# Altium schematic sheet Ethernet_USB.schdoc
size 298 x 196 mm
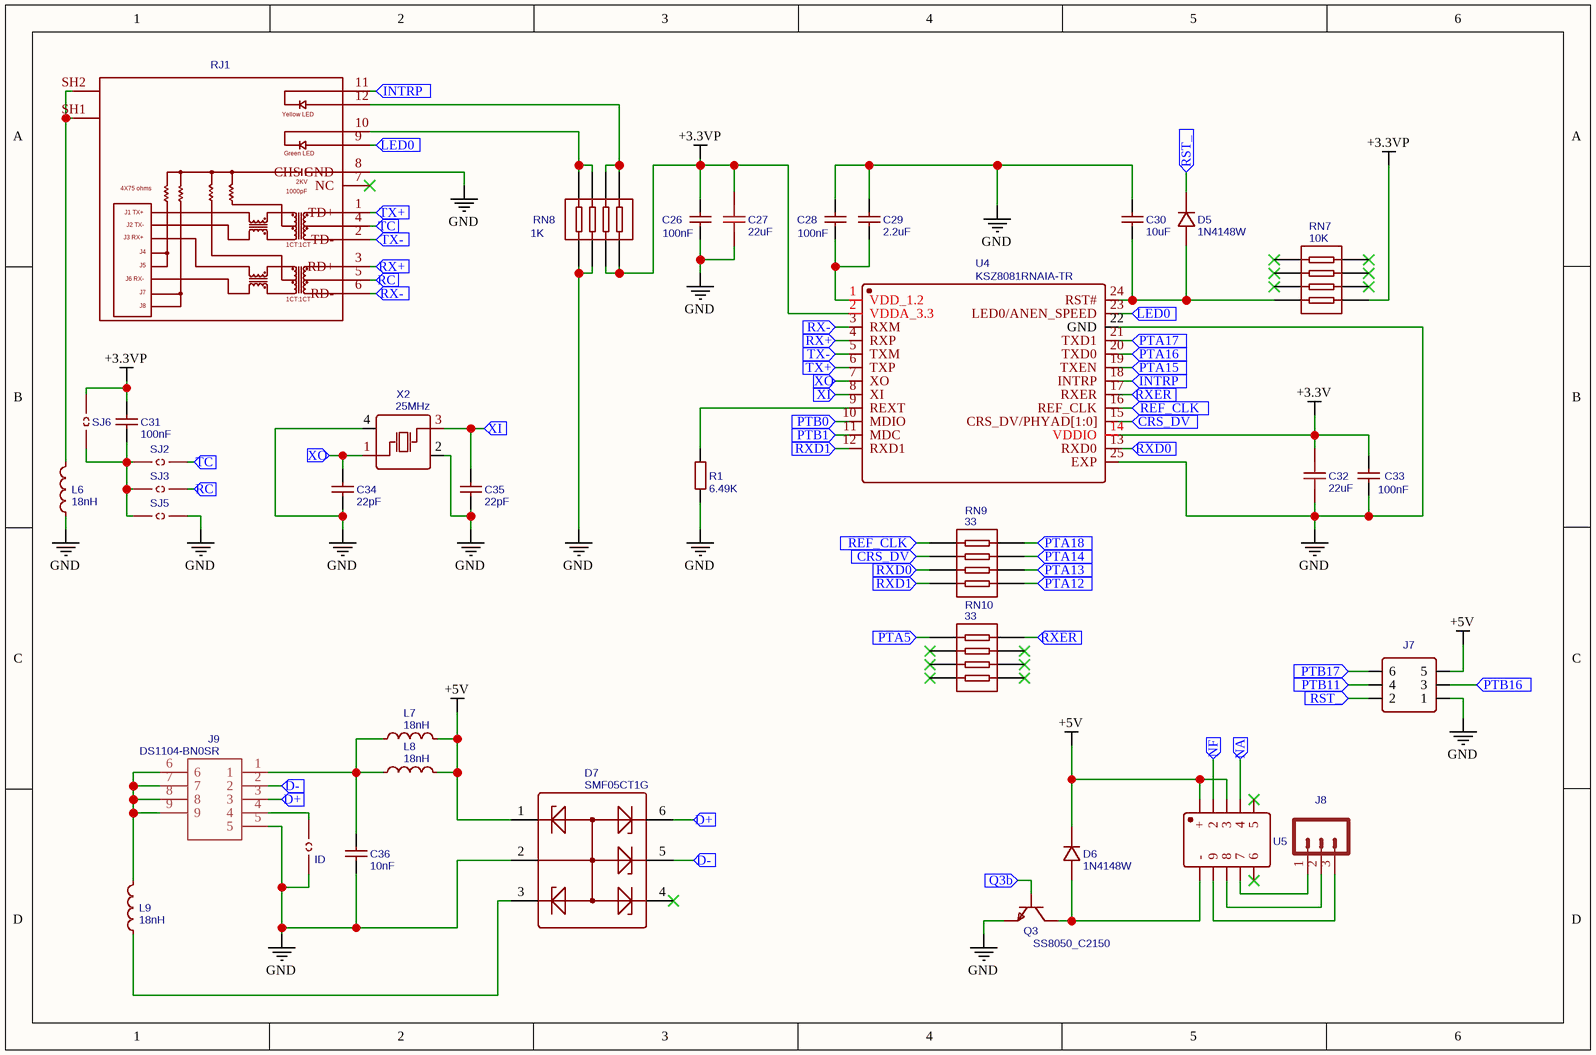
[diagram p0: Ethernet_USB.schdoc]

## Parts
C26  100nF  [C0402]
C27  22uF  [C0805]
C28  100nF  [C0402]
C29  2.2uF  [C0603]
C30  10uF  [C0805]
C31  100nF  [C0402]
C32  22uF  [C0805]
C33  100nF  [C0402]
C34  22pF  [C0402]
C35  22pF  [C0402]
C36  10nF  [C0402]
D5  1N4148W  [SOD-123_L2.8-W1.8-LS3.7-RD]
D6  1N4148W  [SOD-123_L2.8-W1.8-LS3.7-RD]
D7  SMF05CT1G  [SOT-363_L2.0-W1.3-P0.65-LS2.1-TL]
J7  Header-Female-2.54_2x3  [HDR-3X2/2.54]  (value not drawn)
J8  M03POLAR  [MOLEX-1X3]  (value not drawn)
J9  DS1104-BN0SR  [DS1104BN0SR]
L6  18nH  [L0402]
L7  18nH  [L0402]
L8  18nH  [L0402]
L9  18nH  [L0402]
Q3  SS8050_C2150  [SOT-23-3_L2.9-W1.3-P1.90-LS2.4-BR]
R1  6.49K  [R0603]
RJ1  HR911105A_C12074  [RJ45-TH_HR911105A]  (value not drawn)
RN7  10K  [RES-ARRAY-SMD_0402-8P-L2.0-W1.0-BL]
RN8  1K  [RES-ARRAY-SMD_0402-8P-L2.0-W1.0-BL]
RN9  33  [RES-ARRAY-SMD_0402-8P-L2.0-W1.0-BL]
RN10  33  [RES-ARRAY-SMD_0402-8P-L2.0-W1.0-BL]
SJ2  JUMPER-PAD-2-NO  [PAD-JUMPER-2-NO_NO_SILK]  (value not drawn)
SJ3  JUMPER-PAD-2-NO  [PAD-JUMPER-2-NO_NO_SILK]  (value not drawn)
SJ4  ID  [PAD-JUMPER-2-NO_NO_SILK]
SJ5  JUMPER-PAD-2-NO  [PAD-JUMPER-2-NO_NO_SILK]  (value not drawn)
SJ6  JUMPER-PAD-2-NO  [PAD-JUMPER-2-NO_NO_SILK]  (value not drawn)
U4  KSZ8081RNAIA-TR  [QFN-24_L4.0-W4.0-P0.50-BL-EP2.6]
U5  MQ2RC5V  [MQ2RC]  (value not drawn)
X2  25MHz  [OSC-SMD_4P-L3.2-W2.5-BL]

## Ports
CRS_DV (in), D+ (in), D- (in), INTRP (in), LED0 (in), NA (in), NF (in), PTA5 (in), PTA12 (in), PTA13 (in), PTA14 (in), PTA15 (in), PTA16 (in), PTA17 (in), PTA18 (in), PTB0 (in), PTB1 (in), PTB11 (in), PTB16 (in), PTB17 (in), Q3b (in), RC (in), REF_CLK (in), RST_ (in), RX+ (in), RX- (in), RXD0 (in), RXD1 (in), RXER (in), TC (in), TX+ (in), TX- (in), XI (in), XO (in)

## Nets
+3.3V: C32.2 C33.2 U4.14(VDDIO)
+3.3VP: C26.2 C27.1 C31.2 RN7.5 RN8.7 RN8.8 SJ6.2 U4.2(VDDA_3.3)
+5V: D6.1(K) D7.1 J7.5 L7.2 L8.2 U5.1(+) U5.3
GND: C26.1 C27.2 C28.2 C29.2 C30.2 C32.1 C33.1 C34.1 C35.1 C36.1 D7.2 J7.1 J9.5 L6.1 Q3.2(E) R1.1 RJ1.8(CHS_GND) RN8.5 RN8.6 SJ4.1 SJ5.2 U4.22(GND) U4.25(EXP) X2.2(GND) X2.4(GND)
CRS_DV: RN9.2 U4.15(CRS_DV/PHYAD[1:0]) ; port CRS_DV
D+: D7.6 J9.3 ; port D+
D-: D7.5 J9.2 ; port D-
INTRP: RJ1.11 U4.18(INTRP) ; port INTRP
LED0: RJ1.9 U4.23(LED0/ANEN_SPEED) ; port LED0
NA: U5.4 ; port NA
NF: U5.2 ; port NF
PTA5: RN10.1 ; port PTA5
PTA12: RN9.5 ; port PTA12
PTA13: RN9.6 ; port PTA13
PTA14: RN9.7 ; port PTA14
PTA15: U4.19(TXEN) ; port PTA15
PTA16: U4.20(TXD0) ; port PTA16
PTA17: U4.21(TXD1) ; port PTA17
PTA18: RN9.8 ; port PTA18
PTB0: U4.10(MDIO) ; port PTB0
PTB1: U4.11(MDC) ; port PTB1
PTB11: J7.4 ; port PTB11
PTB16: J7.3 ; port PTB16
PTB17: J7.6 ; port PTB17
Q3b: Q3.1(B) ; port Q3b
RC: RJ1.5 SJ3.2 ; port RC
REF_CLK: RN9.1 U4.16(REF_CLK) ; port REF_CLK
RST_: D5.1(K) J7.2 ; port RST_
RX+: RJ1.3(RD+) U4.4(RXP) ; port RX+
RX-: RJ1.6(RD-) U4.3(RXM) ; port RX-
RXD0: RN9.3 U4.13(RXD0) ; port RXD0
RXD1: RN9.4 U4.12(RXD1) ; port RXD1
RXER: RN10.8 U4.17(RXER) ; port RXER
TC: RJ1.4 SJ2.2 ; port TC
TX+: RJ1.1(TD+) U4.6(TXP) ; port TX+
TX-: RJ1.2(TD-) U4.5(TXM) ; port TX-
XI: C35.2 U4.8(XI) X2.3(OSC2) ; port XI
XO: C34.2 U4.7(XO) X2.1(OSC1) ; port XO
NetC28_1: C28.1 C29.1 U4.1(VDD_1.2)
NetC30_1: C30.1 D5.2(A) RN7.4 U4.24(RST#)
NetC31_1: C31.1 SJ2.1 SJ3.1 SJ5.1 SJ6.1
NetC36_2: C36.2 J9.1 L7.1 L8.1
NetD6_2: D6.2(A) Q3.3(C) U5.10(-)
NetD7_3: D7.3 L9.1
NetJ8_1: J8.1 U5.7
NetJ8_2: J8.2 U5.8
NetJ8_3: J8.3 U5.9
NetJ9_4: J9.4 SJ4.2
NetJ9_6: J9.6 J9.7 J9.8 J9.9 L9.2
NetL6_2: L6.2 RJ1.SH1 RJ1.SH2
NetR1_2: R1.2 U4.9(REXT)
NetRJ1_10: RJ1.10 RN8.3 RN8.4
NetRJ1_12: RJ1.12 RN8.1 RN8.2

Not connected (* = marked no-connect by the designer): D7 4*; RJ1 7(NC)*; RN7 1* 2* 3* 6* 7* 8*; RN10 2* 3* 4* 5* 6* 7*; U5 5* 6*

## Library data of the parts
C26 C28 C31 C33 = 100nF: BOM_Manufacturer Part: CL05B104KO5NNNC; BOM_Manufacturer: SAMSUNG; nameAlias: Capacitance; SMT Type: Basic; BOM_Paste Type: base
C27 C32 = 22uF: BOM_Manufacturer: SAMSUNG; BOM_Manufacturer Part: CL21A226MAQNNNE; nameAlias: Capacitance; SMT Type: Basic; BOM_Assembly Type: smtWeld; BOM_Paste Type: base
C29 = 2.2uF: BOM_Manufacturer Part: CL10A225KO8NNNC; BOM_Manufacturer: SAMSUNG; nameAlias: Capacitance; SMT Type: Basic; BOM_Assembly Type: smtWeld; BOM_Paste Type: base
C30 = 10uF: BOM_Manufacturer Part: CL21A106KAYNNNE; BOM_Manufacturer: SAMSUNG; nameAlias: Capacitance; SMT Type: Basic; BOM_Paste Type: base
C34 C35 = 22pF: BOM_Manufacturer: FH; BOM_Manufacturer Part: 0402CG220J500NT; nameAlias: Capacitance; SMT Type: Basic; BOM_Assembly Type: smtWeld; BOM_Paste Type: base
C36 = 10nF: BOM_Manufacturer Part: CL05B103KB5NNNC; BOM_Manufacturer: SAMSUNG; nameAlias: Capacitance; SMT Type: Basic; BOM_Paste Type: base
D5 = 1N4148W: BOM_Manufacturer: SEMTECH; SMT Type: Basic; BOM_Paste Type: base
D6 = 1N4148W: BOM_Manufacturer: SEMTECH; SMT Type: Basic; BOM_Paste Type: base; Package Display: No
D7 = SMF05CT1G: BOM_Manufacturer: ON; SMT Type: Basic; BOM_Assembly Type: smtWeld; BOM_Paste Type: base; Package Display: No
J7 = Header-Female-2.54_2x3: BOM_Manufacturer: CONNFLY; BOM_Manufacturer Part: DS1023-2*3SF11; Contributor: LCSC; Package Display: No
J8 = M03POLAR: description: Header 3; Contributor: SparkFun; Package Display: No
J9 = DS1104-BN0SR: Contributor: kutsiarda; Package Display: No
L6-L9 = 18nH: BOM_Manufacturer: Sunlord; BOM_Manufacturer Part: SDCL1005C18NJTDF; nameAlias: Inductance; SMT Type: Basic; BOM_Paste Type: base
Q3 = SS8050_C2150: BOM_Manufacturer: CJ; BOM_Manufacturer Part: SS8050; SMT Type: Basic; BOM_Assembly Type: smtWeld; BOM_Paste Type: base
R1 = 6.49K: BOM_Manufacturer: UniOhm; BOM_Manufacturer Part: 0603WAF6491T5E; nameAlias: Resistance (Ohms); SMT Type: Extend; BOM_Assembly Type: smtWeld; BOM_Paste Type: expand
RJ1 = HR911105A_C12074: BOM_Manufacturer: HANRUN; BOM_Paste Type: expand; Package Display: No
RN7 = 10K: BOM_Manufacturer: UniOhm; BOM_Manufacturer Part: 4D02WGJ0103TCE; nameAlias: Resistance (Ohms); SMT Type: Basic; BOM_Paste Type: base
RN8 = 1K: BOM_Manufacturer: UniOhm; BOM_Manufacturer Part: 4D02WGJ0102TCE; nameAlias: Resistance (Ohms); SMT Type: Basic; BOM_Paste Type: base
RN9 RN10 = 33: BOM_Manufacturer: UniOhm; BOM_Manufacturer Part: 4D02WGJ0330TCE; nameAlias: Resistance (Ohms); SMT Type: Basic; BOM_Assembly Type: smtWeld; BOM_Paste Type: base
SJ2 SJ3 SJ5 SJ6 = JUMPER-PAD-2-NO: Contributor: SparkFun; Package Display: No
SJ4 = ID: Contributor: SparkFun; Package Display: No
U4 = KSZ8081RNAIA-TR: BOM_Manufacturer: MICROCHIP; Contributor: LCSC; SMT Type: Extend; BOM_Assembly Type: smtWeld; BOM_Paste Type: expand; Package Display: No
U5 = MQ2RC5V: sourceId: YC71jdvpH; Package Display: No
X2 = 25MHz: BOM_Manufacturer: YXC; BOM_Manufacturer Part: X322525MOB4SI; nameAlias: Frequency; SMT Type: Basic; BOM_Assembly Type: smtWeld; BOM_Paste Type: base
